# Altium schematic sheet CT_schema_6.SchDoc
size 278 x 170 mm
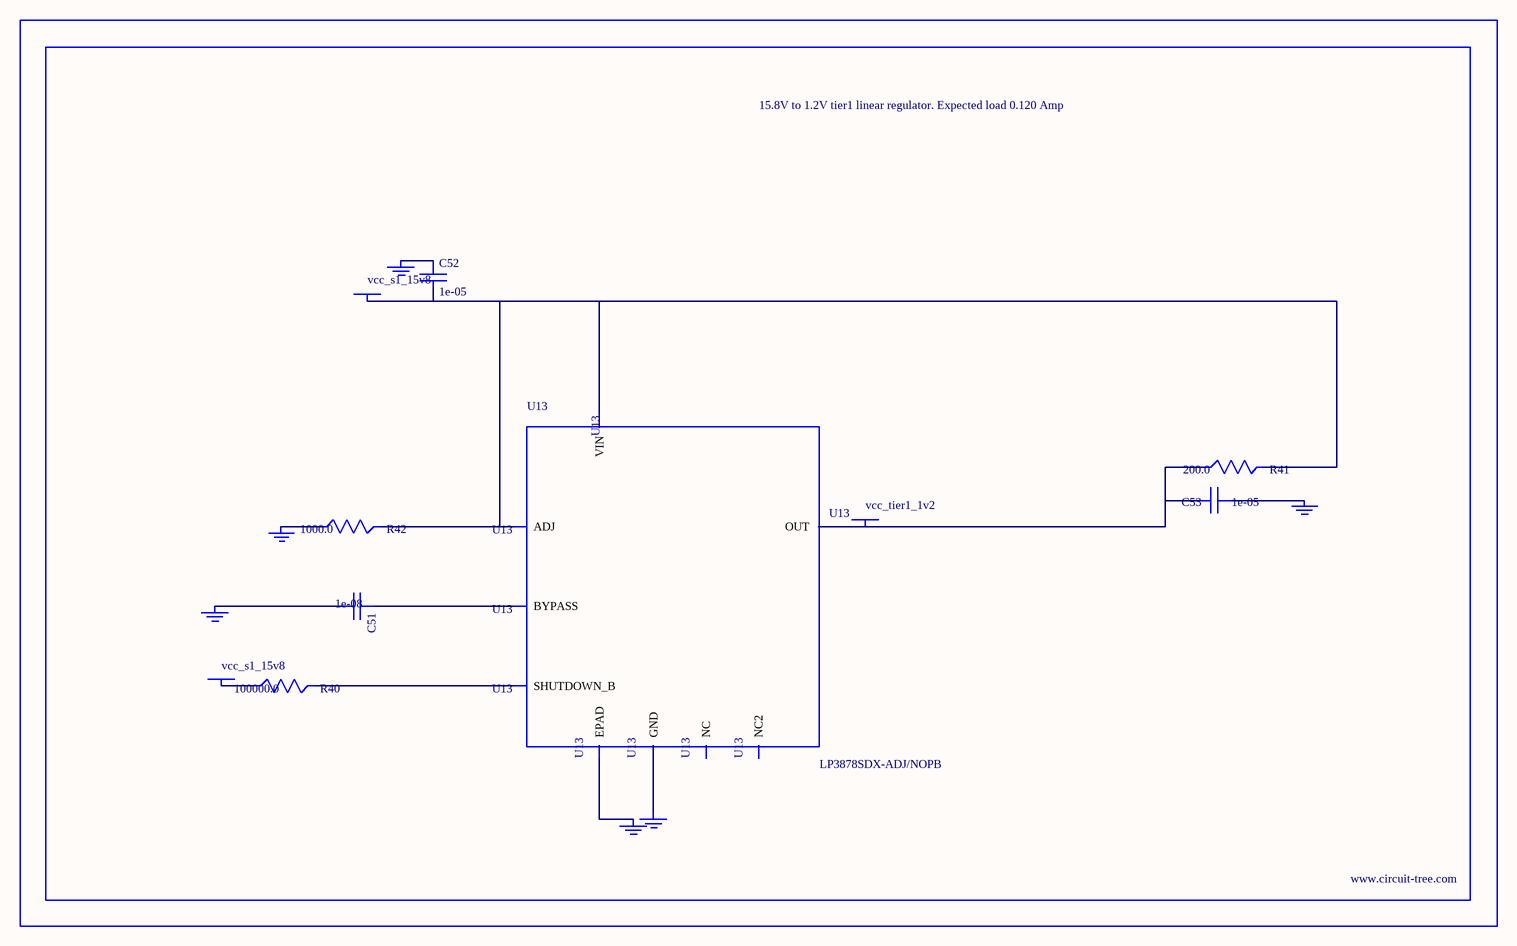
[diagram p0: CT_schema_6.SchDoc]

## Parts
BORDER5  (no value)
C51  1e-08  [C0402]
C52  1e-05  [C1210]
C53  1e-05  [C0805]
GND_INSTANCE_5_0  (no value)
GND_INSTANCE_5_1  (no value)
GND_INSTANCE_5_2  (no value)
GND_INSTANCE_5_3  (no value)
GND_INSTANCE_5_4  (no value)
GND_INSTANCE_5_5  (no value)
POWER_INSTANCE_5_0  vcc_s1_15v8
POWER_INSTANCE_5_1  vcc_s1_15v8
POWER_INSTANCE_5_2  vcc_tier1_1v2
R40  100000.0  [R0603]
R41  200.0  [R0603]
R42  1000.0  [R0603]
U13  LP3878SDX-ADJ/NOPB  [WSON-8]

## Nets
NetC51_1: C51.1 U13.1(BYPASS)
NetC51_2: C51.2 GND_INSTANCE_5_0.0(GND)
NetC52_1: C52.1 GND_INSTANCE_5_1.0(GND)
NetC52_2: C52.2 POWER_INSTANCE_5_0.0(PWR) R41.2 R42.2 U13.4(VIN) U13.6(ADJ)
NetC53_1: C53.1 GND_INSTANCE_5_2.0(GND)
NetC53_2: C53.2 POWER_INSTANCE_5_2.0(PWR) R41.1 U13.5(OUT)
NetGND_INSTANCE_5_3_0: GND_INSTANCE_5_3.0(GND) R42.1
NetGND_INSTANCE_5_4_0: GND_INSTANCE_5_4.0(GND) U13.PAD(EPAD)
NetGND_INSTANCE_5_5_0: GND_INSTANCE_5_5.0(GND) U13.3(GND)
NetPOWER_INSTANCE_5_1_0: POWER_INSTANCE_5_1.0(PWR) R40.1
NetR40_2: R40.2 U13.8(SHUTDOWN_B)

Not connected (* = marked no-connect by the designer): U13 2(NC) 7(NC2)

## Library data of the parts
BORDER5 = BORDER_PAGE5
C51 = C0402C103K3RAC
C52 = C1210C106K5PACTU
C53 = GRM219R60J106ME19D
GND_INSTANCE_5_0-GND_INSTANCE_5_5 = GND
POWER_INSTANCE_5_0-POWER_INSTANCE_5_2 = PWR
R40 = RC0603JR-07100KL
R41 = RC0603JR-07200RL
R42 = RC0603JR-071KL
